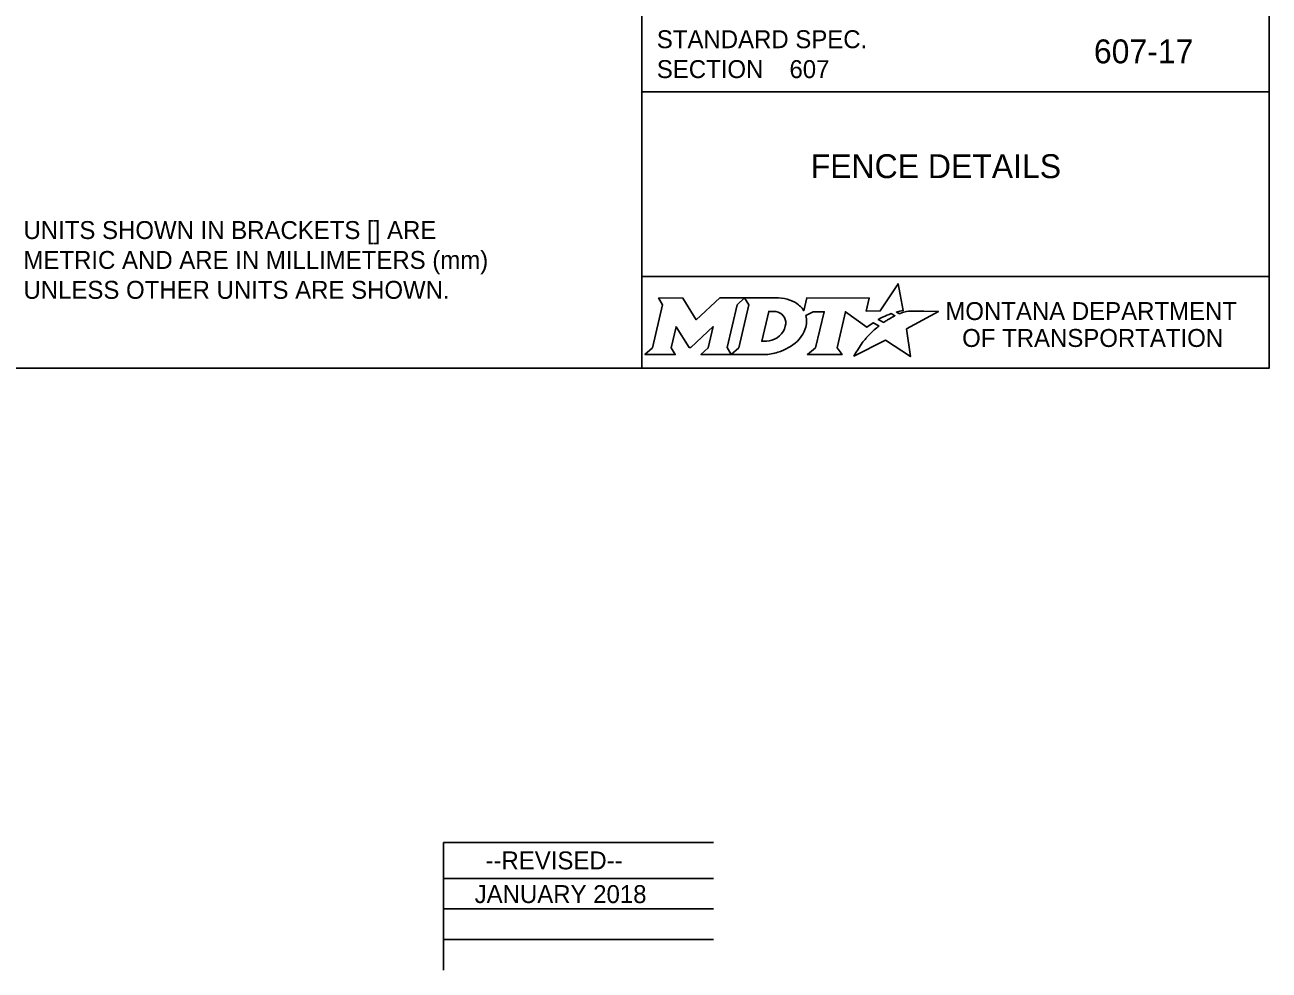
# Model space of a CAD drawing. Extents: x 49991 to 50288, y 49919 to 50011.
# Drawn here: x 50012.585 to 50016.75, y 49985.785 to 49988.947 of the extents above; entities that cross this region are included whole.
import ezdxf

# ---------------------------------------------------------------- set-up
doc = ezdxf.new("R2010")
doc.units = 0
for name, color, linetype in [('Default', 7, 'Continuous'), ('Level 1', 7, 'Continuous'), ('Level 2', 7, 'Continuous'), ('Level 3', 7, 'Continuous'), ('Level 5', 7, 'Continuous')]:
    doc.layers.add(name, color=color, linetype=linetype)

msp = doc.modelspace()

# ---------------------------------------------------------------- linework, layer by layer
at = {"layer": 'Default'}
for points in [[(50015.5126, 49987.9811), (50015.5023, 49987.9867), (50015.5139, 49987.9895), (50015.5255, 49987.9915), (50015.5081, 49988.0816), (50015.4486, 49987.9903), (50015.4013, 49987.9896), (50015.4116, 49988.0337), (50015.2024, 49988.0338), (50015.1923, 49987.9913), (50015.1865, 49987.9996)], [(50014.7056, 49988.0338), (50014.7197, 49988.0104), (50014.6862, 49987.8671), (50014.6605, 49987.8446), (50014.7621, 49987.8446), (50014.7486, 49987.8674), (50014.7648, 49987.9375), (50014.8085, 49987.8685), (50014.8138, 49987.8685), (50014.8889, 49987.938), (50014.8725, 49987.8669), (50014.8478, 49987.8449), (50014.9494, 49987.8449), (50014.9356, 49987.8682), (50014.9688, 49988.0106)], [(50014.9688, 49988.0106), (50014.9941, 49988.0338), (50014.9117, 49988.0338), (50014.8321, 49987.9608), (50014.7876, 49988.0335), (50014.7056, 49988.0338)], [(50015.1077, 49988.0338), (50014.9941, 49988.0338), (50015.0088, 49988.0109), (50014.9749, 49987.8671), (50014.9494, 49987.8449), (50015.06, 49987.8449)], [(50015.1317, 49987.9471), (50015.1305, 49987.939), (50015.1273, 49987.9297), (50015.1231, 49987.9215), (50015.1175, 49987.914), (50015.111, 49987.9071), (50015.1031, 49987.9008), (50015.0948, 49987.8961), (50015.0857, 49987.8922), (50015.0766, 49987.8899), (50015.0674, 49987.889), (50015.0515, 49987.889), (50015.0751, 49987.989), (50015.0911, 49987.989), (50015.0987, 49987.9884), (50015.1063, 49987.9865), (50015.1129, 49987.9835), (50015.119, 49987.9793), (50015.1238, 49987.9743), (50015.1275, 49987.9683), (50015.1302, 49987.9621), (50015.1318, 49987.9547), (50015.1318, 49987.9517), (50015.1317, 49987.9471)], [(50015.1991, 49987.9747), (50015.2237, 49987.9878), (50015.2606, 49987.9878), (50015.232, 49987.8673), (50015.2045, 49987.8446), (50015.3207, 49987.8446), (50015.3037, 49987.8675), (50015.3319, 49987.9877), (50015.4032, 49987.936), (50015.4243, 49987.9511), (50015.444, 49987.9402)], [(50015.3882, 49987.8843), (50015.3729, 49987.8599), (50015.3682, 49987.8524), (50015.3624, 49987.8438), (50015.3601, 49987.8395), (50015.4654, 49987.8926), (50015.5493, 49987.8375), (50015.5362, 49987.9302), (50015.6431, 49987.9886), (50015.5938, 49987.9894), (50015.5637, 49987.9898), (50015.5429, 49987.9901), (50015.5361, 49987.9886), (50015.5312, 49987.9874), (50015.5228, 49987.9851), (50015.5126, 49987.9811)], [(50015.4622, 49987.9535), (50015.4598, 49987.9518), (50015.4415, 49987.9614), (50015.4518, 49987.9671), (50015.4559, 49987.9693), (50015.4645, 49987.9733), (50015.4702, 49987.9759), (50015.4781, 49987.9789), (50015.4854, 49987.9816), (50015.4972, 49987.9742), (50015.4932, 49987.9721), (50015.4886, 49987.9696), (50015.4844, 49987.9674), (50015.4794, 49987.9645), (50015.4775, 49987.9634), (50015.4748, 49987.9618), (50015.4723, 49987.9604), (50015.47, 49987.9588), (50015.4674, 49987.957), (50015.4647, 49987.9552), (50015.4622, 49987.9535)], [(50015.1057, 49987.8522), (50015.1141, 49987.8548), (50015.1271, 49987.8602), (50015.1475, 49987.8712)], [(50015.4021, 49987.9004), (50015.4021, 49987.9004)]]:
    msp.add_lwpolyline(points, dxfattribs=at)
for centre, radius, start, end in [((50015.1308, 49987.9554), 0.0709, 339.5329, 15.8582), ((50015.0868, 49987.9727), 0.1183, 300.9103, 339.1383)]:
    msp.add_arc(centre, radius, start, end, dxfattribs=at)
for centre, major_axis, ratio, start_param, end_param in [((50015.1056, 49987.9864), (0.0834, -0.0037), 0.568097, 0.61298, 1.570796), ((50015.1612, 49987.9937), (0.0361, -0.0295), 0.469099, 1.225588, 1.570796), ((50015.4119, 49987.9106), (-0.0098, -0.0102), 0.016458, 3.141593, 6.279097), ((50015.4329, 49987.9305), (-0.0112, -0.0097), 0.021651, 3.157348, 6.283185), ((50015.3952, 49987.8923), (-0.00694, -0.00806), 0.008222, 0, 3.137361), ((50015.0603, 49987.9932), (0, 0.1484), 0.987302, 3.139398, 3.456847)]:
    msp.add_ellipse(centre, major_axis=major_axis, ratio=ratio, start_param=start_param, end_param=end_param, dxfattribs=at)
at = {"layer": 'Level 1'}
msp.add_lwpolyline([(49999.3835, 49998.9992), (50016.7501, 49998.9992), (50016.7501, 49987.7988), (49999.3835, 49987.7988)], close=True, dxfattribs=at)
msp.add_lwpolyline([(49999.3835, 49998.9992), (50016.7501, 49998.9992), (50016.7501, 49987.7988), (49999.3835, 49987.7988)], close=True, dxfattribs=at)
at = {"layer": 'Level 2'}
msp.add_line((50013.9857, 49985.9989), (50013.9857, 49985.9989), dxfattribs=at)
at = {"layer": 'Level 3'}
for p, q in [((50014.8896, 49986.2124), (50013.9857, 49986.2124)), ((50013.9857, 49986.2124), (50013.9857, 49985.7855)), ((50014.8896, 49986.0924), (50013.9857, 49986.0924)), ((50014.8896, 49985.9901), (50013.9857, 49985.9901)), ((50014.8896, 49985.8878), (50013.9857, 49985.8878))]:
    msp.add_line(p, q, dxfattribs=at)
at = {"layer": 'Level 5'}
for p, q in [((50014.6501, 49989.1988), (50014.6501, 49987.7988)), ((50014.6501, 49989.1988), (50014.6501, 49987.7988)), ((50016.3862, 49988.8587), (50016.3862, 49988.8587)), ((50016.3862, 49988.8587), (50016.3862, 49988.8587)), ((50015.1444, 49988.7993), (50015.1444, 49988.7993)), ((50015.1444, 49988.7993), (50015.1444, 49988.7993)), ((50016.7501, 49988.7238), (50014.6501, 49988.7238)), ((50016.7501, 49988.7238), (50014.6501, 49988.7238)), ((50015.7001, 49988.4747), (50015.7001, 49988.4747)), ((50015.7001, 49988.4747), (50015.7001, 49988.4747)), ((50016.7501, 49988.1057), (50014.6501, 49988.1057)), ((50016.7501, 49988.1057), (50014.6501, 49988.1057))]:
    msp.add_line(p, q, dxfattribs=at)

# ---------------------------------------------------------------- texts
at = {"layer": 'Default'}
for s, p in [('MONTANA DEPARTMENT', (50015.6663, 49987.96)), ('OF TRANSPORTATION', (50015.7225, 49987.87))]:
    msp.add_text(s, height=0.06, dxfattribs=at).set_placement(p)
at = {"layer": 'Level 2'}
for s, height, p in [('607-17', 0.08, (50016.1635, 49988.8187)), ('607', 0.06, (50015.1444, 49988.7693)), ('FENCE DETAILS', 0.08, (50015.2155, 49988.4347)), ('UNITS SHOWN IN BRACKETS [] ARE ', 0.06, (50012.5802, 49988.231)), ('METRIC AND ARE IN MILLIMETERS (mm) ', 0.06, (50012.5802, 49988.131)), ('UNLESS OTHER UNITS ARE SHOWN.', 0.06, (50012.5802, 49988.031)), ('JANUARY 2018', 0.06, (50014.0906, 49986.0097)), ('JANUARY 2018', 0.06, (50014.0906, 49986.0097))]:
    msp.add_text(s, height=height, dxfattribs=at).set_placement(p)
at = {"layer": 'Level 3'}
msp.add_text('--REVISED--', height=0.06, dxfattribs=at).set_placement((50014.1269, 49986.1224))
at = {"layer": 'Level 5'}
for s, p in [('STANDARD SPEC.', (50014.7004, 49988.8694)), ('SECTION', (50014.7004, 49988.7694))]:
    msp.add_text(s, height=0.06, dxfattribs=at).set_placement(p)

doc.saveas('drawing.dxf')
